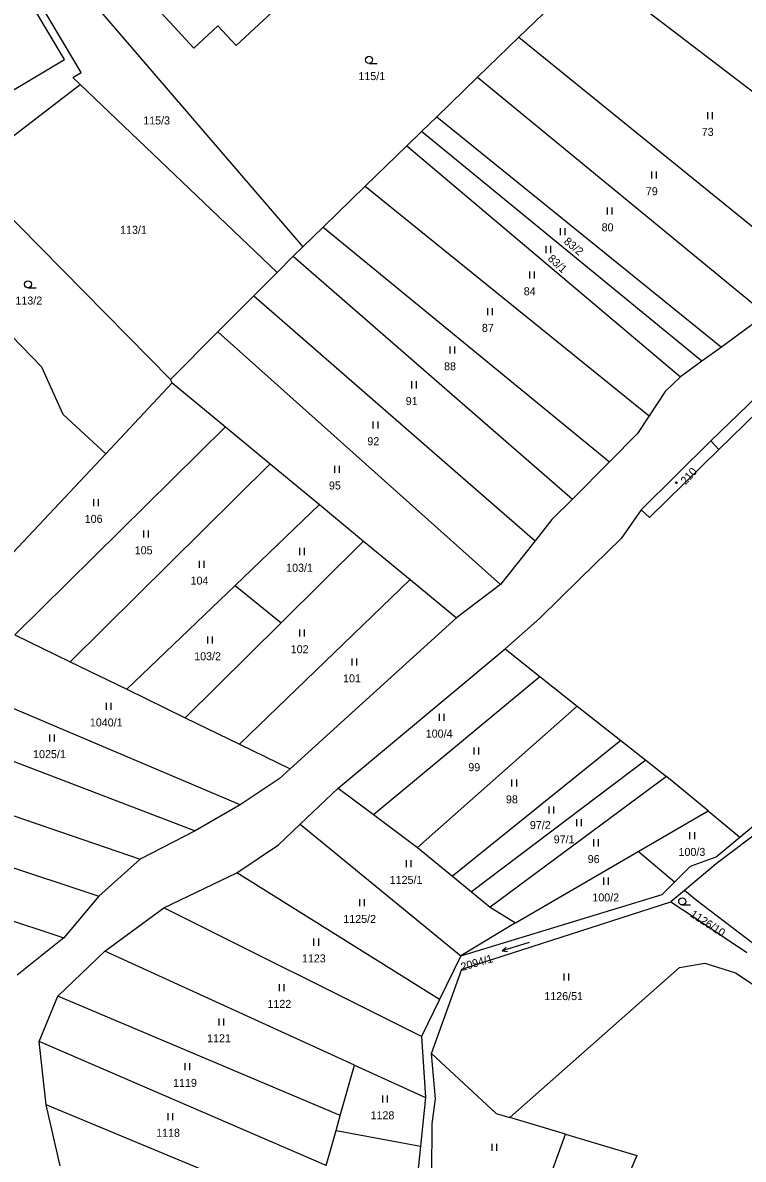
# Model space of a CAD drawing. Extents: x -755528 to -748832, y -1118122 to -1111095.
# Drawn here: x -750929.9 to -750776.9, y -1113743 to -1113501.5 of the extents above; entities that cross this region are included whole.
import ezdxf

# ---------------------------------------------------------------- set-up
doc = ezdxf.new("R2010")
doc.units = 0
for name, color, linetype in [('DZ_DO_ostatní', 7, 'Continuous'), ('DZ_DO_PUPFL', 7, 'Continuous'), ('DZ_NAD_ZPF', 7, 'Continuous'), ('legenda_text', 7, 'Continuous'), ('TZ_UMVŽST', 7, 'Continuous')]:
    doc.layers.add(name, color=color, linetype=linetype)

msp = doc.modelspace()

# ---------------------------------------------------------------- linework, layer by layer
at = {"layer": 'DZ_DO_ostatní'}
for p, q in [((-750921.08, -1113509.29), (-750927.39, -1113498.69)), ((-750932.51, -1113516.09), (-750921.08, -1113509.29))]:
    msp.add_line(p, q, dxfattribs=at)
at = {"layer": 'DZ_NAD_ZPF'}
for p, q in [((-750924.53, -1113486.1), (-750870.47, -1113549.09)), ((-750809.99, -1113489.23), (-750748.48, -1113536.33)), ((-750917.52, -1113512.03), (-750927.75, -1113494.85)), ((-750824.58, -1113504.53), (-750816.01, -1113496.21)), ((-750833.3, -1113513), (-750824.58, -1113504.53)), ((-750824.58, -1113504.53), (-750763.45, -1113554.11)), ((-750841.97, -1113521.42), (-750833.3, -1113513)), ((-750833.3, -1113513), (-750772.47, -1113563.05)), ((-750875.92, -1113554.56), (-750917.73, -1113514.6)), ((-750845.2, -1113524.55), (-750841.97, -1113521.42)), ((-750841.97, -1113521.42), (-750781.53, -1113570.4)), ((-750848.35, -1113527.61), (-750845.2, -1113524.55)), ((-750785.66, -1113573.4), (-750845.2, -1113524.55)), ((-750857.22, -1113536.22), (-750848.35, -1113527.61)), ((-750848.35, -1113527.61), (-750790.19, -1113576.7)), ((-750940.09, -1113535.08), (-750898.58, -1113577.28)), ((-750866.15, -1113544.89), (-750857.22, -1113536.22)), ((-750857.22, -1113536.22), (-750796.87, -1113585.01)), ((-750870.47, -1113549.09), (-750866.15, -1113544.89)), ((-750866.15, -1113544.89), (-750805.29, -1113594.76)), ((-750872.46, -1113551.09), (-750870.47, -1113549.09)), ((-750875.92, -1113554.56), (-750872.46, -1113551.09)), ((-750872.46, -1113551.09), (-750813.18, -1113602.67)), ((-750880.87, -1113559.52), (-750875.92, -1113554.56)), ((-750888.5, -1113567.17), (-750880.87, -1113559.52)), ((-750880.87, -1113559.52), (-750821.1, -1113611.56)), ((-750898.58, -1113577.28), (-750888.5, -1113567.17)), ((-750888.5, -1113567.17), (-750828.42, -1113620.8)), ((-750781.53, -1113570.4), (-750785.66, -1113573.4)), ((-750785.66, -1113573.4), (-750790.19, -1113576.7)), ((-750912.31, -1113593.03), (-750898.21, -1113577.99)), ((-750898.21, -1113577.99), (-750898.58, -1113577.28)), ((-750898.21, -1113577.99), (-750886.9, -1113587.33)), ((-750886.9, -1113587.33), (-750931.61, -1113631.5)), ((-750886.9, -1113587.33), (-750877.35, -1113595.22)), ((-750783.74, -1113590.32), (-750798.57, -1113604.95)), ((-750782.05, -1113592.11), (-750783.74, -1113590.32)), ((-750942.2, -1113624.91), (-750912.31, -1113593.03)), ((-750877.35, -1113595.22), (-750919.85, -1113637.24)), ((-750877.35, -1113595.22), (-750866.91, -1113603.85)), ((-750805.29, -1113594.76), (-750813.18, -1113602.67)), ((-750866.91, -1113603.85), (-750884.85, -1113621.06)), ((-750866.91, -1113603.85), (-750857.52, -1113611.61)), ((-750857.52, -1113611.61), (-750875.05, -1113628.97)), ((-750857.52, -1113611.61), (-750847.65, -1113619.76)), ((-750821.1, -1113611.56), (-750828.42, -1113620.8)), ((-750847.65, -1113619.76), (-750883.91, -1113654.76)), ((-750847.65, -1113619.76), (-750837.77, -1113627.93)), ((-750884.85, -1113621.06), (-750907.82, -1113643.1)), ((-750884.85, -1113621.06), (-750875.05, -1113628.97)), ((-750828.42, -1113620.8), (-750837.77, -1113627.93)), ((-750875.05, -1113628.97), (-750895.42, -1113649.15)), ((-750837.77, -1113627.93), (-750873.12, -1113660.02)), ((-750820.15, -1113628.07), (-750827.47, -1113634.53)), ((-750931.61, -1113631.5), (-750919.85, -1113637.24)), ((-750862.93, -1113664.09), (-750827.47, -1113634.53)), ((-750827.47, -1113634.53), (-750820.08, -1113640.38)), ((-750883.75, -1113667.61), (-750954.25, -1113637.76)), ((-750919.85, -1113637.24), (-750907.82, -1113643.1)), ((-750855.41, -1113669.72), (-750820.08, -1113640.38)), ((-750820.08, -1113640.38), (-750812.15, -1113646.65)), ((-751043.8, -1113643.99), (-750913.77, -1113687.08)), ((-750907.82, -1113643.1), (-750895.42, -1113649.15)), ((-750962.85, -1113646.56), (-750893.3, -1113673.19)), ((-750812.15, -1113646.65), (-750846.07, -1113676.71)), ((-750812.15, -1113646.65), (-750802.92, -1113653.95)), ((-750895.42, -1113649.15), (-750883.91, -1113654.76)), ((-750802.92, -1113653.95), (-750838.66, -1113682.8)), ((-750802.92, -1113653.95), (-750797.59, -1113658.16)), ((-751045.92, -1113654.35), (-750921.19, -1113695.93)), ((-750883.91, -1113654.76), (-750873.12, -1113660.02)), ((-750797.59, -1113658.16), (-750834.62, -1113686.13)), ((-750797.59, -1113658.16), (-750793.18, -1113661.65)), ((-750793.18, -1113661.65), (-750830.67, -1113689.37)), ((-750784.36, -1113668.95), (-750793.18, -1113661.65)), ((-750871.01, -1113671.78), (-750862.93, -1113664.09)), ((-750862.93, -1113664.09), (-750855.41, -1113669.72)), ((-750883.75, -1113667.61), (-750893.3, -1113673.19)), ((-750855.41, -1113669.72), (-750846.07, -1113676.71)), ((-750799.22, -1113677.59), (-750784.36, -1113668.95)), ((-750784.36, -1113668.95), (-750777.63, -1113674.52)), ((-750893.3, -1113673.19), (-750905, -1113679.17)), ((-750871.01, -1113671.78), (-750836.87, -1113699.72)), ((-750846.07, -1113676.71), (-750838.66, -1113682.8)), ((-750825.27, -1113692.73), (-750799.22, -1113677.59)), ((-750791.45, -1113684.09), (-750799.22, -1113677.59)), ((-750905, -1113679.17), (-750913.77, -1113687.08)), ((-750900, -1113689.55), (-750884.45, -1113682.07)), ((-750841.39, -1113708.99), (-750884.45, -1113682.07)), ((-750838.66, -1113682.8), (-750834.62, -1113686.13)), ((-750794.07, -1113686.72), (-750791.45, -1113684.09)), ((-750913.77, -1113687.08), (-750921.19, -1113695.93)), ((-750836.87, -1113699.72), (-750794.07, -1113686.72)), ((-750834.62, -1113686.13), (-750830.67, -1113689.37)), ((-750789.37, -1113685.83), (-750792.25, -1113688.26)), ((-750912.51, -1113698.74), (-750900, -1113689.55)), ((-750845.23, -1113716.87), (-750900, -1113689.55)), ((-750830.67, -1113689.37), (-750825.27, -1113692.73)), ((-750825.27, -1113692.73), (-750836.87, -1113699.72)), ((-750921.19, -1113695.93), (-750931.14, -1113703.83)), ((-750922.47, -1113708.29), (-750912.51, -1113698.74)), ((-750859.44, -1113722.94), (-750912.51, -1113698.74)), ((-750836.87, -1113699.72), (-750841.39, -1113708.99)), ((-750926.49, -1113717.9), (-750922.47, -1113708.29)), ((-750862.49, -1113733.69), (-750922.47, -1113708.29)), ((-750841.39, -1113708.99), (-750845.23, -1113716.87)), ((-750924.97, -1113731.36), (-750926.49, -1113717.9)), ((-750865.51, -1113744.31), (-750926.49, -1113717.9)), ((-750845.23, -1113716.87), (-750844.35, -1113729.82)), ((-750862.49, -1113733.69), (-750859.44, -1113722.94)), ((-750859.44, -1113722.94), (-750844.35, -1113729.82)), ((-750844.35, -1113729.82), (-750845.43, -1113740.16)), ((-750922, -1113744.36), (-750924.97, -1113731.36)), ((-750868.5, -1113754.85), (-750924.97, -1113731.36)), ((-750863.39, -1113736.86), (-750862.49, -1113733.69)), ((-750814.65, -1113737.62), (-750826.5, -1113734.07)), ((-750865.51, -1113744.31), (-750863.39, -1113736.86)), ((-750863.39, -1113736.86), (-750845.43, -1113740.16)), ((-750823.92, -1113763.01), (-750814.65, -1113737.62)), ((-750814.65, -1113737.62), (-750799.48, -1113742.17)), ((-750845.43, -1113740.16), (-750847.12, -1113756.34))]:
    msp.add_line(p, q, dxfattribs=at)
for points in [[(-750699.74, -1113446.69), (-750699.88, -1113447.82), (-750705.94, -1113496.13), (-750711.3, -1113516.41), (-750720.58, -1113539.49), (-750741.81, -1113549.88), (-750760.15, -1113567.55), (-750783.74, -1113590.32)], [(-750908.84, -1113482.27), (-750912.98, -1113485.25), (-750908.3, -1113491.75), (-750907.86, -1113491.43), (-750902.96, -1113496.73), (-750893.61, -1113506.86), (-750888.47, -1113502.11), (-750884.58, -1113506.31), (-750874.94, -1113497.39), (-750856.94, -1113495.71), (-750852.76, -1113490.88), (-750846.95, -1113495.52), (-750840.99, -1113488.07), (-750865.03, -1113468.92), (-750868.95, -1113465.8)], [(-750917.73, -1113514.6), (-750919.31, -1113513.09), (-750917.52, -1113512.03)], [(-750940.09, -1113535.08), (-750935.15, -1113530.56), (-750936.48, -1113528.94), (-750917.73, -1113514.6)], [(-750912.31, -1113593.03), (-750921.37, -1113584.7), (-750925.91, -1113574.64), (-750960.34, -1113539.18)], [(-750709.08, -1113578.88), (-750738.02, -1113549.2), (-750782.05, -1113592.11)], [(-750772.47, -1113563.05), (-750775.33, -1113565.85), (-750781.53, -1113570.4)], [(-750790.19, -1113576.7), (-750793.46, -1113579.79), (-750796.87, -1113585.01)], [(-750796.87, -1113585.01), (-750799.31, -1113588.76), (-750805.29, -1113594.76)], [(-750798.57, -1113604.95), (-750796.81, -1113606.62), (-750782.05, -1113592.11)], [(-750777.63, -1113674.52), (-750763.63, -1113662.92), (-750765.9, -1113661.59), (-750760.75, -1113654.81), (-750748.79, -1113643.61), (-750737.64, -1113630.95), (-750728.23, -1113622.83), (-750726.05, -1113621.76), (-750713.49, -1113610.1), (-750705.61, -1113600.25), (-750696.21, -1113591.97)], [(-750813.18, -1113602.67), (-750817.51, -1113607.02), (-750821.1, -1113611.56)], [(-750798.57, -1113604.95), (-750802.8, -1113611.03), (-750811.68, -1113619.66), (-750820.15, -1113628.07)], [(-751031.24, -1113636.11), (-750966, -1113658.29), (-750905, -1113679.17)], [(-750754.06, -1113651.68), (-750761.99, -1113661.68), (-750761.24, -1113664.04), (-750782.63, -1113680.15), (-750789.37, -1113685.83)], [(-750873.12, -1113660.02), (-750875.46, -1113662.15), (-750883.75, -1113667.61)], [(-750884.45, -1113682.07), (-750875.6, -1113676.14), (-750871.01, -1113671.78)], [(-750791.45, -1113684.09), (-750788.08, -1113680.7), (-750782.65, -1113678.68), (-750777.63, -1113674.52)], [(-750774.99, -1113696.94), (-750786.88, -1113687.91), (-750789.37, -1113685.83)], [(-750843.08, -1113720.49), (-750836.64, -1113702.58), (-750792.25, -1113688.26)], [(-750792.25, -1113688.26), (-750787.32, -1113691.54), (-750776.12, -1113698.99)], [(-750826.5, -1113734.07), (-750790.45, -1113702.22), (-750785.05, -1113701.29), (-750778.52, -1113703.37), (-750715.91, -1113744.93)], [(-750843.07, -1113746.06), (-750842.98, -1113735.4), (-750842.29, -1113730.12), (-750843.08, -1113720.49)], [(-750843.08, -1113720.49), (-750829.36, -1113733.21), (-750826.5, -1113734.07)], [(-750799.48, -1113742.17), (-750808.46, -1113763.02), (-750818.01, -1113781.04)]]:
    msp.add_lwpolyline(points, dxfattribs=at)
at = {"layer": 'legenda_text'}
msp.add_circle((-750791.0768, -1113599.1992), 0.175, dxfattribs=at)
at = {"layer": 'TZ_UMVŽST'}
for p, q in [((-750856.373, -1113510.1), (-750854.623, -1113510.1)), ((-750784.431, -1113521.95), (-750784.431, -1113520.45)), ((-750783.43, -1113521.95), (-750783.43, -1113520.45)), ((-750796.301, -1113534.56), (-750796.301, -1113533.06)), ((-750795.3, -1113534.56), (-750795.3, -1113533.06)), ((-750805.701, -1113542.23), (-750805.701, -1113540.73)), ((-750804.7, -1113542.23), (-750804.7, -1113540.73)), ((-750815.711, -1113546.62), (-750815.711, -1113545.12)), ((-750814.71, -1113546.62), (-750814.71, -1113545.12)), ((-750818.731, -1113550.4), (-750818.731, -1113548.9)), ((-750817.73, -1113550.4), (-750817.73, -1113548.9)), ((-750822.241, -1113555.82), (-750822.241, -1113554.32)), ((-750821.24, -1113555.82), (-750821.24, -1113554.32)), ((-750928.833, -1113557.79), (-750927.083, -1113557.79)), ((-750831.131, -1113563.6), (-750831.131, -1113562.1)), ((-750830.13, -1113563.6), (-750830.13, -1113562.1)), ((-750839.161, -1113571.76), (-750839.161, -1113570.26)), ((-750838.16, -1113571.76), (-750838.16, -1113570.26)), ((-750847.311, -1113579.15), (-750847.311, -1113577.65)), ((-750846.31, -1113579.15), (-750846.31, -1113577.65)), ((-750855.471, -1113587.69), (-750855.471, -1113586.19)), ((-750854.47, -1113587.69), (-750854.47, -1113586.19)), ((-750863.631, -1113597.09), (-750863.631, -1113595.59)), ((-750862.63, -1113597.09), (-750862.63, -1113595.59)), ((-750914.871, -1113604.18), (-750914.871, -1113602.68)), ((-750913.87, -1113604.18), (-750913.87, -1113602.68)), ((-750904.241, -1113610.86), (-750904.241, -1113609.36)), ((-750903.24, -1113610.86), (-750903.24, -1113609.36)), ((-750871.101, -1113614.57), (-750871.101, -1113613.07)), ((-750870.1, -1113614.57), (-750870.1, -1113613.07)), ((-750892.371, -1113617.29), (-750892.371, -1113615.79)), ((-750891.37, -1113617.29), (-750891.37, -1113615.79)), ((-750890.641, -1113633.37), (-750890.641, -1113631.87)), ((-750889.64, -1113633.37), (-750889.64, -1113631.87)), ((-750871.101, -1113631.88), (-750871.101, -1113630.38)), ((-750870.1, -1113631.88), (-750870.1, -1113630.38)), ((-750859.981, -1113638.07), (-750859.981, -1113636.57)), ((-750858.98, -1113638.07), (-750858.98, -1113636.57)), ((-750912.151, -1113647.44), (-750912.151, -1113645.94)), ((-750911.15, -1113647.44), (-750911.15, -1113645.94)), ((-750841.441, -1113649.82), (-750841.441, -1113648.32)), ((-750840.44, -1113649.82), (-750840.44, -1113648.32)), ((-750924.211, -1113654.17), (-750924.211, -1113652.67)), ((-750923.21, -1113654.17), (-750923.21, -1113652.67)), ((-750834.021, -1113656.95), (-750834.021, -1113655.45)), ((-750833.02, -1113656.95), (-750833.02, -1113655.45)), ((-750826.011, -1113663.78), (-750826.011, -1113662.28)), ((-750825.01, -1113663.78), (-750825.01, -1113662.28)), ((-750818.101, -1113669.47), (-750818.101, -1113667.97)), ((-750817.1, -1113669.47), (-750817.1, -1113667.97)), ((-750812.251, -1113672.21), (-750812.251, -1113670.71)), ((-750811.25, -1113672.21), (-750811.25, -1113670.71)), ((-750808.651, -1113676.47), (-750808.651, -1113674.97)), ((-750807.65, -1113676.47), (-750807.65, -1113674.97)), ((-750788.191, -1113674.95), (-750788.191, -1113673.45)), ((-750787.19, -1113674.95), (-750787.19, -1113673.45)), ((-750848.451, -1113680.89), (-750848.451, -1113679.39)), ((-750847.45, -1113680.89), (-750847.45, -1113679.39)), ((-750806.511, -1113684.62), (-750806.511, -1113683.12)), ((-750805.51, -1113684.62), (-750805.51, -1113683.12)), ((-750858.311, -1113689.19), (-750858.311, -1113687.69)), ((-750857.31, -1113689.19), (-750857.31, -1113687.69)), ((-750789.843, -1113688.92), (-750788.093, -1113688.92)), ((-750868.071, -1113697.58), (-750868.071, -1113696.08)), ((-750867.07, -1113697.58), (-750867.07, -1113696.08)), ((-750822.33, -1113696.89), (-750828.068, -1113698.644)), ((-750828.068, -1113698.644), (-750827.28, -1113697.879)), ((-750828.068, -1113698.644), (-750826.987, -1113698.838)), ((-750814.911, -1113704.99), (-750814.911, -1113703.49)), ((-750813.91, -1113704.99), (-750813.91, -1113703.49)), ((-750875.391, -1113707.24), (-750875.391, -1113705.74)), ((-750874.39, -1113707.24), (-750874.39, -1113705.74)), ((-750888.221, -1113714.55), (-750888.221, -1113713.05)), ((-750887.22, -1113714.55), (-750887.22, -1113713.05)), ((-750895.441, -1113724.02), (-750895.441, -1113722.52)), ((-750894.44, -1113724.02), (-750894.44, -1113722.52)), ((-750853.481, -1113730.91), (-750853.481, -1113729.41)), ((-750852.48, -1113730.91), (-750852.48, -1113729.41)), ((-750899.031, -1113734.63), (-750899.031, -1113733.13)), ((-750898.03, -1113734.63), (-750898.03, -1113733.13)), ((-750830.211, -1113741.15), (-750830.211, -1113739.65)), ((-750829.21, -1113741.15), (-750829.21, -1113739.65))]:
    msp.add_line(p, q, dxfattribs=at)
for centre in [(-750856.3729, -1113509.3498), (-750928.8329, -1113557.0398), (-750789.8429, -1113688.1698)]:
    msp.add_circle(centre, 0.75, dxfattribs=at)

# ---------------------------------------------------------------- texts
at = {"layer": 'DZ_DO_PUPFL'}
for s, p in [('115/1', (-750858.63, -1113513.65)), ('115/3', (-750904.35, -1113523.08)), ('73', (-750785.696, -1113525.5)), ('79', (-750797.566, -1113538.11)), ('113/1', (-750909.26, -1113546.31)), ('80', (-750806.966, -1113545.78)), ('113/2', (-750931.5, -1113561.34)), ('84', (-750823.506, -1113559.37)), ('87', (-750832.396, -1113567.15)), ('88', (-750840.436, -1113575.31)), ('91', (-750848.576, -1113582.7)), ('92', (-750856.736, -1113591.24)), ('95', (-750864.896, -1113600.64)), ('106', (-750916.785, -1113607.73)), ('105', (-750906.155, -1113614.41)), ('103/1', (-750873.988, -1113618.12)), ('104', (-750894.285, -1113620.84)), ('102', (-750873.015, -1113635.43)), ('103/2', (-750893.528, -1113636.92)), ('101', (-750861.895, -1113641.62)), ('1040/1', (-750915.687, -1113650.99)), ('100/4', (-750844.328, -1113653.37)), ('1025/1', (-750927.747, -1113657.72)), ('99', (-750835.286, -1113660.5)), ('98', (-750827.286, -1113667.33)), ('97/2', (-750822.209, -1113672.8)), ('97/1', (-750817.139, -1113675.83)), ('100/3', (-750790.63, -1113678.5)), ('96', (-750809.916, -1113680.02)), ('1125/1', (-750851.987, -1113684.44)), ('100/2', (-750808.93, -1113688.17)), ('1125/2', (-750861.847, -1113692.74)), ('1123', (-750870.634, -1113701.13)), ('1122', (-750877.954, -1113710.79)), ('1126/51', (-750819.136, -1113709.14)), ('1121', (-750890.784, -1113718.1)), ('1119', (-750898.004, -1113727.57)), ('1128', (-750856.054, -1113734.46)), ('1118', (-750901.604, -1113738.18))]:
    msp.add_text(s, height=1.7, dxfattribs=at).set_placement(p)
for s, rotation, p in [('83/2', 320, (-750815.135, -1113548.188)), ('83/1', 317, (-750818.537, -1113551.764)), ('210', 47, (-750789.138, -1113599.729)), ('1126/10', 327, (-750788.302, -1113691.282)), ('2094/1', 16, (-750836.62, -1113702.955))]:
    msp.add_text(s, height=1.7, rotation=rotation, dxfattribs=at).set_placement(p)

doc.saveas('drawing.dxf')
